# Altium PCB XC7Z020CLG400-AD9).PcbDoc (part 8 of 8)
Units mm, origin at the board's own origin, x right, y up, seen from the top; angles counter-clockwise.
Board outline 38 x 38 mm, 14 copper layers (Top Layer, GND02, ART03, PWR04, ART05, GND06, ART07, ART08, PWR09, ART10, GND11, ART12, PWR13, Bottom Layer); 276 components, 302 nets, 1684 pads, 1576 vias.
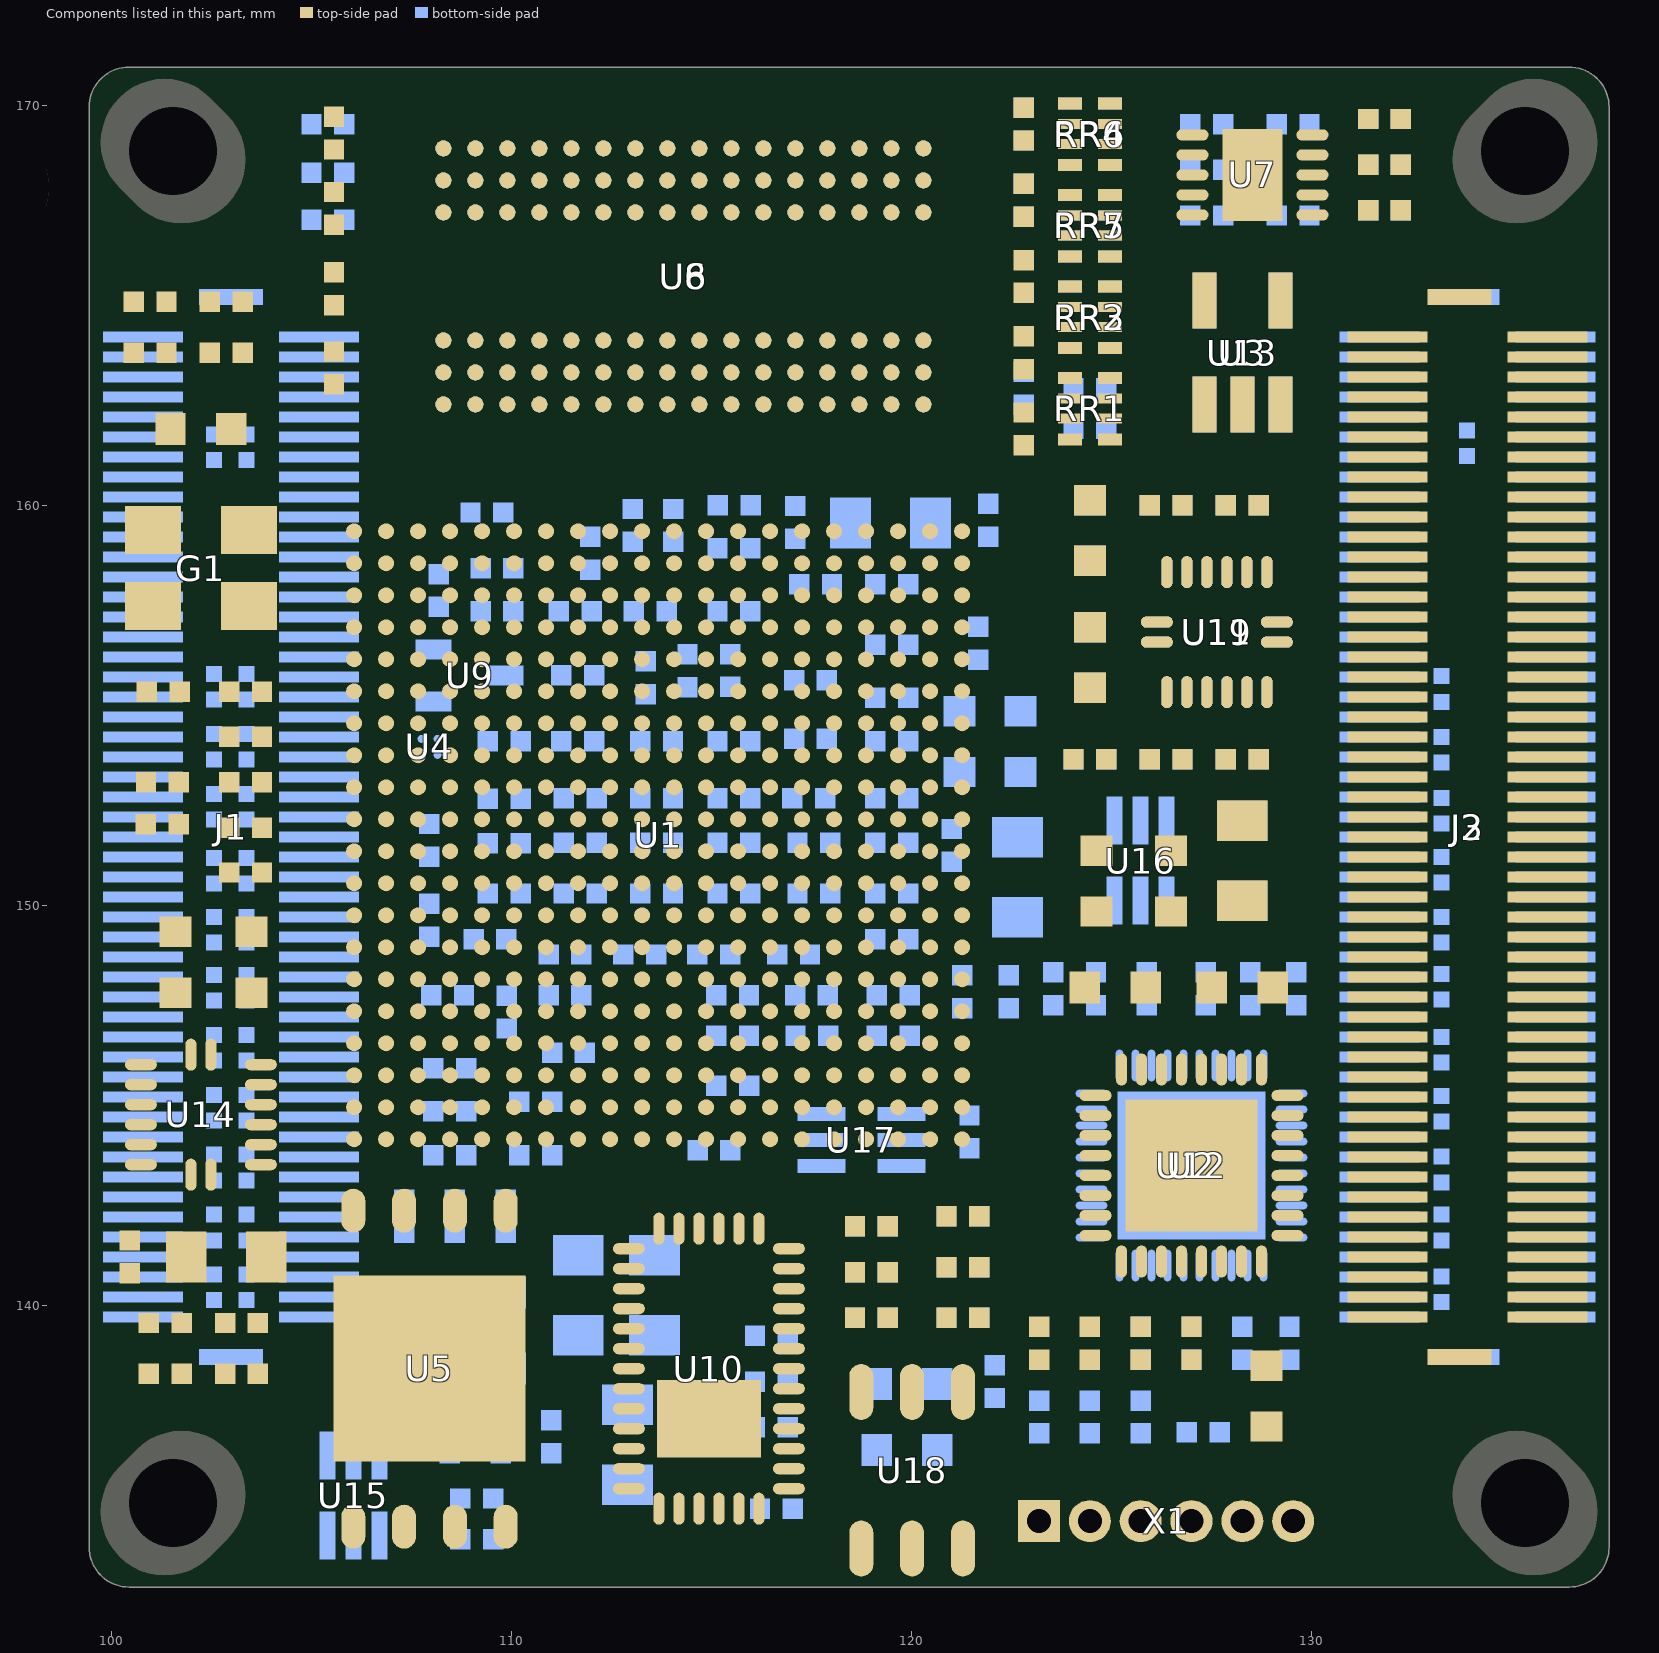
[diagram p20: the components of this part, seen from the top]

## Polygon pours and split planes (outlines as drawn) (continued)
VCC-IN on ART03 "TOP-No Net" (solid, remove dead copper, pour order 1000): 100.838,142.875 100.711,142.748 100.711,140.843 100.838,140.716 101.854,140.716 101.981,140.843 101.981,142.748 101.854,142.875
VCC-IN on ART05 "TOP-No Net" (solid, remove dead copper, pour order 1001): 102.235,141.986 100.584,141.986 100.457,141.859 100.457,141.478 100.457,137.541 100.711,137.287 100.965,137.287 103.505,137.287 103.886,136.906 103.886,136.398 103.886,133.858 104.14,133.604 104.394,133.604 114.046,133.604 114.173,133.731 114.173,133.858 114.173,135.128 113.919,135.382 113.538,135.382 111.887,135.382 111.125,136.144 107.823,139.446 104.013,139.446 103.886,139.446 103.505,139.827 103.378,139.954 103.378,140.97 103.378,141.605 102.997,141.986
BANK34_VCC on PWR13 "TOP-No Net" (solid, remove dead copper, pour order 1003): 136.398,161.29 128.905,161.29 121.285,153.67 116.078,153.67 111.506,149.098 111.506,134.112 110.998,133.604 105.156,133.604 104.902,133.858 104.902,146.558 107.188,148.844 107.188,155.194 112.522,160.528 122.428,160.528 128.524,166.624 136.398,166.624 136.652,166.37 136.652,161.544
BANK35_VCC on PWR13 "TOP-No Net" (solid, remove dead copper, pour order 1002): 136.398,161.036 129.286,161.036 121.412,153.162 116.332,153.162 111.76,148.59 111.76,133.858 112.014,133.604 132.588,133.604 133.096,134.112 133.096,136.652 133.858,137.414 136.398,137.414 136.652,137.668 136.652,160.782
GND on PWR13 "TOP-No Net" (solid, remove dead copper, pour order 1004): 106.68,155.677 106.68,149.098 104.394,146.812 104.394,137.668 104.14,137.414 100.584,137.414 100.33,137.668 100.33,166.37 100.584,166.624 103.632,166.624 103.886,166.878 103.886,169.926 104.14,170.18 132.842,170.18 133.096,169.926 133.096,167.386 132.842,167.132 128.27,167.132 122.174,161.036 112.039,161.036
GND on GND02 "TOP-No Net" (solid, remove dead copper, pour order 1005): 133.122,170.092 104.674,170.092 104.42,169.838 104.42,166.79 103.912,166.282 100.864,166.282 100.61,166.028 100.61,137.326 100.864,137.072 104.166,137.072 104.42,136.818 104.42,133.516 104.674,133.262 133.122,133.262 133.376,133.516 133.376,136.31 134.138,137.072 135.408,137.072 137.186,137.072 137.44,137.326 137.44,166.028 137.186,166.282 134.138,166.282 133.63,166.79 133.63,169.838 133.376,170.092
VCC-IN on PWR04 (split plane): 136.537,170.451 136.629,170.423 136.714,170.378 136.789,170.317 136.85,170.242 136.895,170.157 136.923,170.065 136.932,169.981 136.931,169.969 136.931,133.969 136.932,133.957 136.923,133.873 136.895,133.781 136.85,133.696 136.789,133.621 136.714,133.56 136.629,133.515 136.537,133.487 136.453,133.478 136.441,133.479 127.339,133.479 127.339,140.469 127.33,140.535 127.305,140.597 127.264,140.65 124.767,143.147 124.767,155.677 124.758,155.743 124.733,155.805 124.692,155.858 123.898,156.652 123.844,156.693 123.783,156.718 123.716,156.727 121.495,156.727 121.429,156.718 121.367,156.693 121.314,156.652 119.865,155.203 109.608,155.203 109.542,155.194 109.48,155.169 109.427,155.128 101.756,147.457 101.715,147.404 101.69,147.342 101.681,147.276 101.681,146.057 101.69,145.991 101.715,145.929 101.756,145.876 107.598,140.034 107.651,139.993 107.695,139.975 107.713,139.968 107.779,139.959 118.087,139.959 118.699,139.347 118.699,133.479 100.441,133.479 100.429,133.478 100.345,133.487 100.253,133.515 100.168,133.56 100.093,133.621 100.032,133.696 99.987,133.781 99.959,133.873 99.95,133.957 99.951,133.969 99.951,169.969 99.95,169.981 99.959,170.065 99.987,170.157 100.032,170.242 100.093,170.317 100.168,170.378 100.253,170.423 100.345,170.451 100.429,170.46 100.441,170.459 122.001,170.459 122.001,162.313 122.01,162.247 122.035,162.185 122.076,162.132 122.838,161.37 122.891,161.329 122.953,161.304 123.019,161.295 126.575,161.295 126.641,161.304 126.703,161.329 126.756,161.37 127.518,162.132 127.559,162.185 127.584,162.247 127.593,162.313 127.593,170.459 136.441,170.459 136.453,170.46
VCC-1V8 on PWR04 (split plane): 124.255,155.57 124.255,143.041 124.263,142.975 124.289,142.913 124.33,142.86 126.827,140.363 126.827,133.479 119.211,133.479 119.211,139.453 119.202,139.519 119.177,139.581 119.136,139.634 118.374,140.396 118.321,140.437 118.259,140.462 118.193,140.471 107.885,140.471 102.193,146.163 102.193,147.17 109.714,154.691 119.971,154.691 120.037,154.7 120.099,154.725 120.152,154.766 121.601,156.215 123.61,156.215
AVTT on PWR04 (split plane): 127.081,162.419 126.469,161.807 123.125,161.807 122.513,162.419 122.513,170.459 127.081,170.459
GND on GND06 (split plane): 136.537,170.451 136.629,170.423 136.714,170.378 136.789,170.317 136.85,170.242 136.895,170.157 136.923,170.065 136.932,169.981 136.931,169.969 136.931,133.969 136.932,133.957 136.923,133.873 136.895,133.781 136.85,133.696 136.789,133.621 136.714,133.56 136.629,133.515 136.537,133.487 136.453,133.478 136.441,133.479 100.441,133.479 100.429,133.478 100.345,133.487 100.253,133.515 100.168,133.56 100.093,133.621 100.032,133.696 99.987,133.781 99.959,133.873 99.95,133.957 99.951,133.969 99.951,169.969 99.95,169.981 99.959,170.065 99.987,170.157 100.032,170.242 100.093,170.317 100.168,170.378 100.253,170.423 100.345,170.451 100.429,170.46 100.441,170.459 136.441,170.459 136.453,170.46
BANK13_VCC on PWR09 (split plane): 136.537,170.451 136.629,170.423 136.714,170.378 136.789,170.317 136.85,170.242 136.895,170.157 136.923,170.065 136.932,169.981 136.931,169.969 136.931,133.969 136.932,133.957 136.923,133.873 136.895,133.781 136.85,133.696 136.789,133.621 136.714,133.56 136.629,133.515 136.537,133.487 136.453,133.478 136.441,133.479 100.441,133.479 100.429,133.478 100.345,133.487 100.253,133.515 100.168,133.56 100.093,133.621 100.032,133.696 99.987,133.781 99.959,133.873 99.95,133.957 99.951,133.969 99.951,169.969 99.95,169.981 99.959,170.065 99.987,170.157 100.032,170.242 100.093,170.317 100.168,170.378 100.253,170.423 100.345,170.451 100.429,170.46 100.441,170.459 106.888,170.459 106.888,166.229 105.947,165.288 105.906,165.235 105.881,165.173 105.872,165.107 105.872,157.106 105.881,157.04 105.906,156.978 105.947,156.925 106.589,156.283 106.642,156.242 106.686,156.224 106.704,156.217 106.77,156.208 108.797,156.208 109.5,155.505 109.462,155.456 109.437,155.394 109.428,155.328 109.428,152.03 108.284,150.886 108.243,150.833 108.218,150.772 108.209,150.705 108.209,148.23 108.209,144.849 108.218,144.783 108.243,144.721 108.284,144.668 111.154,141.798 113.204,139.747 113.258,139.707 113.319,139.681 113.386,139.672 115.367,139.672 115.433,139.681 115.495,139.707 115.548,139.747 118.621,142.821 118.662,142.874 118.688,142.936 118.696,143.002 118.696,152.545 118.703,152.596 118.703,155.095 119.136,155.528 121.295,157.687 121.335,157.739 123.687,157.739 123.727,157.687 123.78,157.646 123.842,157.621 123.908,157.612 123.974,157.621 124.036,157.646 124.089,157.687 124.47,158.068 124.511,158.121 124.536,158.183 124.545,158.249 124.545,159.9 124.536,159.966 124.524,159.997 124.511,160.028 124.47,160.081 123.446,161.105 123.446,170.459 136.441,170.459 136.453,170.46
AHVDD_CA on PWR09 (split plane): 122.934,160.999 122.943,160.933 122.968,160.871 123.009,160.818 124.033,159.794 124.033,158.355 123.727,158.049 123.687,157.998 121.335,157.998 121.295,158.049 121.242,158.09 121.18,158.115 121.114,158.124 121.048,158.115 120.986,158.09 120.933,158.049 118.774,155.89 118.447,155.563 118.12,155.89 118.067,155.931 118.005,155.956 117.939,155.965 110.065,155.965 109.999,155.956 109.937,155.931 109.884,155.89 109.862,155.868 109.085,156.645 109.032,156.686 108.97,156.711 108.903,156.72 106.876,156.72 106.384,157.212 106.384,165.001 107.325,165.942 107.366,165.995 107.384,166.039 107.391,166.057 107.4,166.123 107.4,170.459 122.934,170.459
VCC-1V0 on PWR09 (split plane): 118.191,155.095 118.191,152.655 118.184,152.603 118.184,143.108 115.261,140.185 113.492,140.185 111.516,142.16 108.721,144.955 108.721,148.23 108.721,150.599 109.865,151.743 109.906,151.796 109.931,151.858 109.94,151.924 109.94,155.222 110.171,155.453 117.833,155.453
GND on GND11 (split plane): 136.537,170.451 136.629,170.423 136.714,170.378 136.789,170.317 136.85,170.242 136.895,170.157 136.923,170.065 136.932,169.981 136.931,169.969 136.931,133.969 136.932,133.957 136.923,133.873 136.895,133.781 136.85,133.696 136.789,133.621 136.714,133.56 136.629,133.515 136.537,133.487 136.453,133.478 136.441,133.479 100.441,133.479 100.429,133.478 100.345,133.487 100.253,133.515 100.168,133.56 100.093,133.621 100.032,133.696 99.987,133.781 99.959,133.873 99.95,133.957 99.951,133.969 99.951,169.969 99.95,169.981 99.959,170.065 99.987,170.157 100.032,170.242 100.093,170.317 100.168,170.378 100.253,170.423 100.345,170.451 100.429,170.46 100.441,170.459 136.441,170.459 136.453,170.46

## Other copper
Top Layer:
  region net ADDRVREF: 130.721,166.726 130.721,167.259 129.95,167.259 129.95,166.726
  region net BANK13_VCC: 127.419,164.649 127.419,165.665 126.492,165.665 126.492,164.649
  region net GND: 132.88,166.554 132.88,167.316 131.991,167.316 131.991,166.554
  region net VCC-1V8: 103.81,146.812 103.81,147.93 103.276,147.93 103.276,146.812
  region net VCC-1V8: 103.607,147.549 103.607,148.031 100.889,148.031 100.889,147.549
  region net VCC-1V8: 101.956,147.015 101.956,147.83 101.346,147.83 101.346,147.015
  region net GND: 103.759,149.35 103.759,150.165 103.226,150.165 103.226,149.35
  region net GND: 104.445,149.149 104.445,149.555 100.749,149.555 100.749,149.149
  region net GND: 101.778,149.149 101.778,150.266 101.371,150.266 101.371,149.149
  region net VCC-IN: 101.87,141.224 101.87,142.443 101.041,142.443 101.041,141.224
  region net VCC-IN: 101.057,141.58 101.057,142.443 100.305,142.443 100.305,141.58
  region net BANK13_VCC: 124.739,156.642 124.739,158.826 124.155,158.826 124.155,156.642
  region net BANK13_VCC: 125.499,156.722 125.499,157.226 123.495,157.226 123.495,156.722
  region net BANK13_VCC: 125.349,158.369 125.349,158.826 124.155,158.826 124.155,158.369
  region net ADDRVREF: 131.394,166.624 131.394,167.443 130.663,167.443 130.663,166.624
  region: 103.641,167.769 cw(c102.641,167.769) 102.641,166.769 99.641,166.769 99.641,169.769 cw(c100.641,169.769) 100.641,170.769 103.641,170.769
  region: 134.241,166.769 cw(c134.241,167.769) 133.241,167.769 133.241,170.769 136.241,170.769 cw(c136.241,169.769) 137.241,169.769 137.241,166.769
  region: 133.241,136.169 cw(c134.241,136.169) 134.241,137.169 137.241,137.169 137.241,134.169 cw(c136.241,134.169) 136.241,133.169 133.241,133.169
  region: 102.641,137.169 cw(c102.641,136.169) 103.641,136.169 103.641,133.169 100.641,133.169 cw(c100.641,134.169) 99.641,134.169 99.641,137.169
  text "PCB联盟网（www.pcbbar.com），EDA技术学习好帮手！QQ群：610359600" at 98,90.5 h3
PWR13:
  rectangle net VCC-IN: 100.457,162.509 102.362,163.932
Bottom Layer:
  region net GND: 114.071,137.525 114.071,139.122 112.573,139.122 112.573,137.525
  region net GND: 113.957,138.995 113.957,139.503 111.163,139.503 111.163,138.995
  region net VCC-1V0: 113.957,141.154 113.957,141.662 111.417,141.662 111.417,141.154
  region net VCC-1V0: 113.957,141.154 113.957,142.24 113.322,142.24 113.322,141.154
  region net BANK13_VCC: 130.048,164.903 130.048,165.411 129.22,165.411 129.22,164.903
  region net AHVDD_CA: 124.752,156.97 124.752,158.934 124.244,158.934 124.244,156.97
  region net AHVDD_CA: 125.26,156.667 125.26,157.283 124.638,157.283 124.638,156.667
  region net VCC-1V0: 113.576,141.478 113.576,142.24 111.354,142.24 111.354,141.478
  region net GND: 112.979,137.135 112.979,137.77 111.76,137.77 111.76,137.135
  region net GND: 112.014,138.287 112.014,139.217 111.328,139.217 111.328,138.287
  region net GND: 113.309,136.5 113.309,137.525 112.573,137.525 112.573,136.5
  region net VCC-IN: 113.309,134.264 113.309,135.407 112.446,135.407 112.446,134.264
  region net VCC-IN: 114.097,135.255 114.097,135.87 111.848,135.87 111.848,135.255
  region net AHVDD_CA: 125.374,157.912 125.374,158.648 123.647,158.648 123.647,157.912
  region net AHVDD_CA: 125.374,156.267 125.374,157.785 124.435,157.785 124.435,156.267
  region: 102.641,137.169 cw(c102.641,136.169) 103.641,136.169 103.641,133.169 100.641,133.169 cw(c100.641,134.169) 99.641,134.169 99.641,137.169
  region: 133.241,136.169 cw(c134.241,136.169) 134.241,137.169 137.241,137.169 137.241,134.169 cw(c136.241,134.169) 136.241,133.169 133.241,133.169
  region: 134.241,166.769 cw(c134.241,167.769) 133.241,167.769 133.241,170.769 136.241,170.769 cw(c136.241,169.769) 137.241,169.769 137.241,166.769
  region: 103.641,167.769 cw(c102.641,167.769) 102.641,166.769 99.641,166.769 99.641,169.769 cw(c100.641,169.769) 100.641,170.769 103.641,170.769
PWR09 (plane layer: these items are gaps in the copper):
  lines w0.254: 121.114,157.868 123.908,157.868
  lines w0.508: 107.144,170.969 107.144,166.123 106.128,165.107 106.128,157.106 106.77,156.464 108.903,156.464 109.862,155.506 ; 121.114,157.868 118.955,155.709 118.447,155.201 ; 123.19,170.969 123.19,160.999 124.289,159.9 124.289,158.249 123.908,157.868 ; 118.447,155.201 118.447,152.596 118.44,152.603 118.44,143.002 115.367,139.929 113.386,139.929 111.335,141.979 108.465,144.849 108.465,148.23 108.465,150.705 109.684,151.924 109.684,155.328 110.065,155.709 117.939,155.709 118.447,155.201
PWR04 (plane layer: these items are gaps in the copper):
  lines w0.508: 118.955,132.969 118.955,139.453 118.193,140.215 107.779,140.215 101.937,146.057 101.937,147.276 109.608,154.947 119.971,154.947 121.495,156.471 123.716,156.471 124.511,155.677 124.511,143.041 127.083,140.469 127.083,132.969 ; 122.257,170.969 122.257,162.313 123.019,161.551 126.575,161.551 127.337,162.313 127.337,170.969

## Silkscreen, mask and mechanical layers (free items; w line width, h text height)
Mechanical 1:
  the board outline again, w0.152
Drill Drawing:
  lines w0.127: 175.441,95.969 175.441,169.969
  lines w0.152: 99.441,95.969 ccw(c100.441,95.969) 100.441,94.969 136.441,94.969 ccw(c136.441,95.969) 137.441,95.969 ; 99.441,95.969 cw(c98.441,95.969) 98.441,94.969 97.441,94.969 95.441,94.969 cw(c95.441,95.969) 94.441,95.969 94.441,169.969 cw(c95.441,169.969) 95.441,170.969 98.441,170.969 cw(c98.441,169.969) 99.441,169.969 99.441,131.969 ; 99.441,95.969 99.441,131.969 ; 99.441,95.969 99.441,131.969 ; 99.441,131.969 cw(c100.441,131.969) 100.441,132.969 136.441,132.969 cw(c136.441,131.969) 137.441,131.969 ; 137.441,95.969 ccw(c138.441,95.969) 138.441,94.969 174.441,94.969 ccw(c174.441,95.969) 175.441,95.969 ; 137.441,95.969 137.441,131.969 ; 137.441,95.969 137.441,131.969 ; 137.441,131.969 cw(c138.441,131.969) 138.441,132.969 ; 138.441,132.969 cw(c138.441,133.969) 137.441,133.969 137.441,169.969 cw(c138.441,169.969) 138.441,170.969 174.441,170.969 cw(c174.441,169.969) 175.441,169.969 ; 138.441,132.969 174.441,132.969 ; 138.441,132.969 174.441,132.969 ; 174.441,132.969 ccw(c174.441,133.969) 175.441,133.969 175.441,169.969 ; 174.441,132.969 cw(c174.441,131.969) 175.441,131.969 175.441,95.969 ; 175.441,95.969 ccw(c176.441,95.969) 176.441,94.969 177.441,94.969 179.441,94.969 ccw(c179.441,95.969) 180.441,95.969 180.441,169.969 ccw(c179.441,169.969) 179.441,170.969 176.441,170.969 ccw(c176.441,169.969) 175.441,169.969
  text "X0BMC031A0" at 99.441,175.514 h1.27

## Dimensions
99.441,169.969 to 137.441,169.969 on Drill Drawing
100.441,170.969 to 100.441,132.969 on Drill Drawing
